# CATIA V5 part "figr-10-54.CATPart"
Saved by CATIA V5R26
Part number: Part1
Bounding box of the stored display mesh (mm): x 0 to 100, y -43.492 to 31.433, z -3.653 to 11.537
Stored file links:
  D:\_Deepak\CATIA\CATIA V5-6R2016_Deepak\Resources\Part files\Partfiles\c10_catia_v5_6r2016_prt\figr-10-54.CATPart
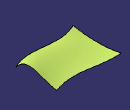
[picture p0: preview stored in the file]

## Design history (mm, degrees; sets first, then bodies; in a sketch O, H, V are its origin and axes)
Set1
  Sketch1 on yz-plane, origin (0, 0, 0), H (0, 1, 0), V (0, 0, 1)
  Plane1: type Offset, RefPlane yz-plane, Offset 100
  Sketch2 on xy-plane, origin (0, 0, 0), H (1, 0, 0), V (0, 1, 0)
    spline S1 through (0, 31.0443) (19.7053, 31.0443) (51.809, 26.4574) (100, 31.0443)
    reference intersected line E1 through (100, 0) direction (0, 1) from Plane1
    point P1 (0, 31.0443)
    point P2 (100, 31.0443)
    coincidence: P1 V, P2 E1
  Sketch3 on xy-plane, origin (0, 0, 0), H (1, 0, 0), V (0, 1, 0)
    spline S1 through (0, -43.492) (26.209, -36.2295) (80.3728, -38.1407) (100, -32.0249)
    reference intersected line E1 through (100, 0) direction (0, 1) from Plane1
    point P1 (0, -43.492)
    point P2 (100, -32.0249)
    coincidence: P1 V, P2 E1
  Sketch4 on Plane1, origin (100, 0, 0), H (0, 1, 0), V (0, 0, 1)
    spline S1 through (-32.0249, 0) (-14.5305, 11.3827) (11.9668, 5.3652) (31.0443, 0)
    reference projected point E1 (31.0443, 0) from vertex of Sketch2
    reference projected point E2 (-32.0249, 0) from vertex of Sketch3
    point P1 (-32.0249, 0)
    point P2 (31.0443, 0)
    coincidence: P1 H, P2 H, P2 E1, P1 E2
  Sketch5 on yz-plane, origin (0, 0, 0), H (0, 1, 0), V (0, 0, 1)
    spline S1 through (31.0443, 0) (7.4727, -3.1675) (-43.492, 0)
    reference projected point E1 (-43.492, 0) from vertex of Sketch3
    reference projected point E2 (31.0443, 0) from vertex of Sketch2
    point P1 (31.0443, 0)
    point P2 (-43.492, 0)
    coincidence: P1 H, P2 H, P2 E1, P1 E2
  Fill1: Boundary (Sketch5; Sketch3; Sketch4; Sketch2)
Body1 (main body)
